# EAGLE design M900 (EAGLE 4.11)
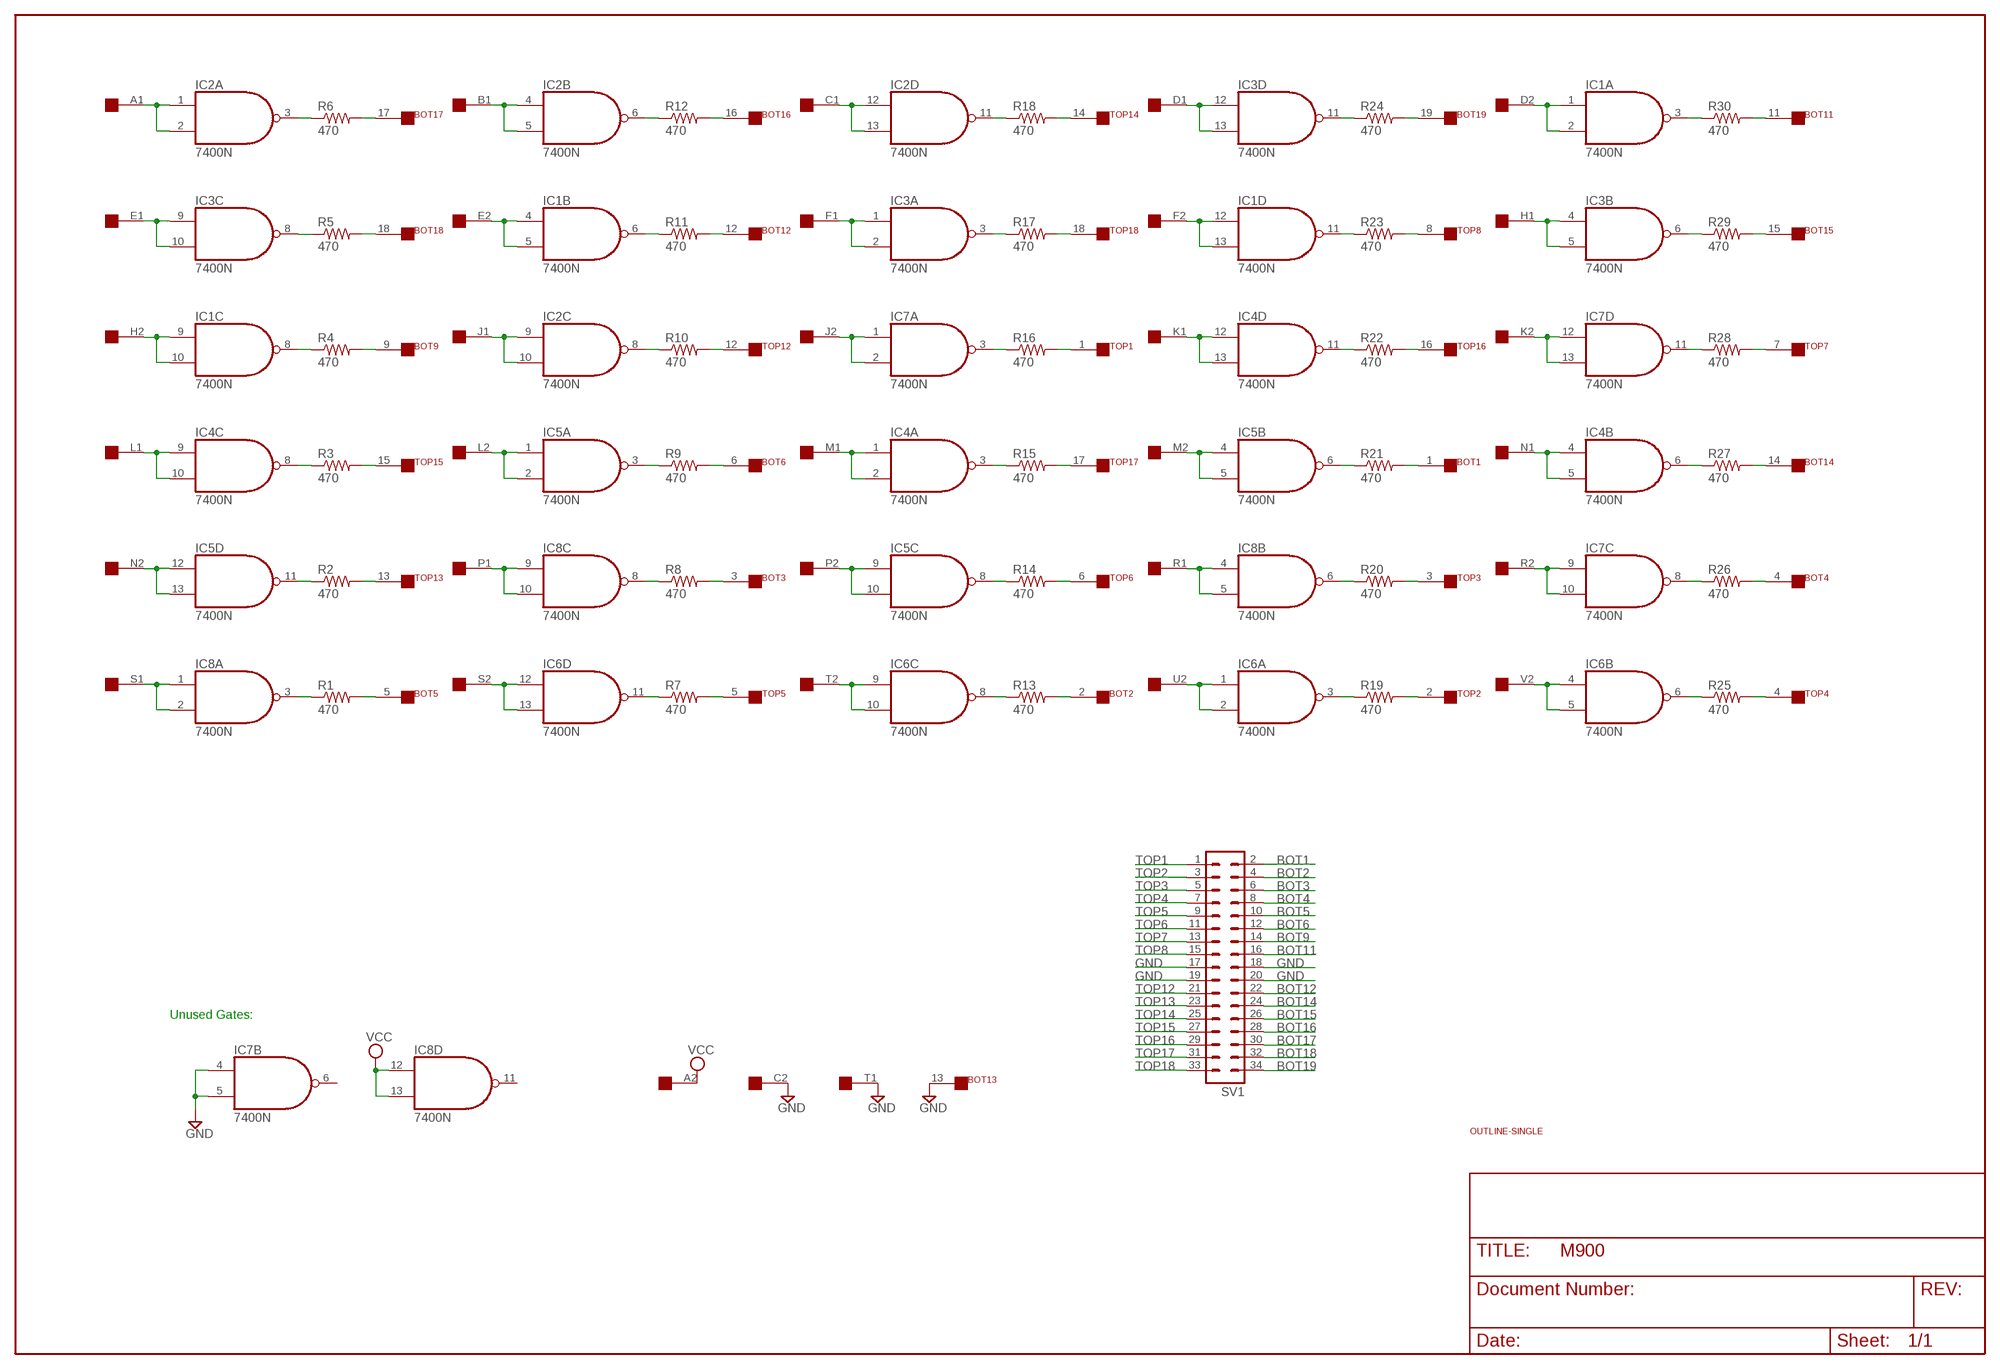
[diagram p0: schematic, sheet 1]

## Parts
BOT  FLEX19  [FLEX19]
EDGE  SINGLE  [EDGE-CON2]
IC1  7400N  [DIL14]
IC2  7400N  [DIL14]
IC3  7400N  [DIL14]
IC4  7400N  [DIL14]
IC5  7400N  [DIL14]
IC6  7400N  [DIL14]
IC7  7400N  [DIL14]
IC8  7400N  [DIL14]
R1  470  R-US_0207/10  [0207/10]
R2  470  R-US_0207/10  [0207/10]
R3  470  R-US_0207/10  [0207/10]
R4  470  R-US_0207/10  [0207/10]
R5  470  R-US_0207/10  [0207/10]
R6  470  R-US_0207/10  [0207/10]
R7  470  R-US_0207/10  [0207/10]
R8  470  R-US_0207/10  [0207/10]
R9  470  R-US_0207/10  [0207/10]
R10  470  R-US_0207/10  [0207/10]
R11  470  R-US_0207/10  [0207/10]
R12  470  R-US_0207/10  [0207/10]
R13  470  R-US_0207/10  [0207/10]
R14  470  R-US_0207/10  [0207/10]
R15  470  R-US_0207/10  [0207/10]
R16  470  R-US_0207/10  [0207/10]
R17  470  R-US_0207/10  [0207/10]
R18  470  R-US_0207/10  [0207/10]
R19  470  R-US_0207/10  [0207/10]
R20  470  R-US_0207/10  [0207/10]
R21  470  R-US_0207/10  [0207/10]
R22  470  R-US_0207/10  [0207/10]
R23  470  R-US_0207/10  [0207/10]
R24  470  R-US_0207/10  [0207/10]
R25  470  R-US_0207/10  [0207/10]
R26  470  R-US_0207/10  [0207/10]
R27  470  R-US_0207/10  [0207/10]
R28  470  R-US_0207/10  [0207/10]
R29  470  R-US_0207/10  [0207/10]
R30  470  R-US_0207/10  [0207/10]
SV1  MA17-2  [MA17-2]
TOP  FLEX19  [FLEX19]
U$2  OUTLINE-SINGLE  [SINGLE]

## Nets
BOT1: BOT.1 R21.2 SV1.2
BOT2: BOT.2 R13.2 SV1.4
BOT3: BOT.3 R8.2 SV1.6
BOT4: BOT.4 R26.2 SV1.8
BOT5: BOT.5 R1.2 SV1.10
BOT6: BOT.6 R9.2 SV1.12
BOT9: BOT.9 R4.2 SV1.14
BOT11: BOT.11 R30.2 SV1.16
BOT12: BOT.12 R11.2 SV1.22
BOT14: BOT.14 R27.2 SV1.24
BOT15: BOT.15 R29.2 SV1.26
BOT16: BOT.16 R12.2 SV1.28
BOT17: BOT.17 R6.2 SV1.30
BOT18: BOT.18 R5.2 SV1.32
BOT19: BOT.19 R24.2 SV1.34
GND [supply]: BOT.13 EDGE.C2 EDGE.T1 IC7.4(B:I0) IC7.5(B:I1) SV1.17 SV1.18 SV1.19 SV1.20
N$1: EDGE.A1 IC2.1(A:I0) IC2.2(A:I1)
N$2: IC2.3(A:O) R6.1
N$3: IC3.8(C:O) R5.1
N$4: IC1.8(C:O) R4.1
N$5: IC4.8(C:O) R3.1
N$6: IC5.11(D:O) R2.1
N$7: EDGE.H2 IC1.9(C:I0) IC1.10(C:I1)
N$8: EDGE.S1 IC8.1(A:I0) IC8.2(A:I1)
N$9: EDGE.N2 IC5.12(D:I0) IC5.13(D:I1)
N$10: EDGE.L1 IC4.9(C:I0) IC4.10(C:I1)
N$11: EDGE.E1 IC3.9(C:I0) IC3.10(C:I1)
N$12: EDGE.P1 IC8.9(C:I0) IC8.10(C:I1)
N$13: EDGE.B1 IC2.4(B:I0) IC2.5(B:I1)
N$14: EDGE.E2 IC1.4(B:I0) IC1.5(B:I1)
N$15: EDGE.J1 IC2.9(C:I0) IC2.10(C:I1)
N$16: EDGE.L2 IC5.1(A:I0) IC5.2(A:I1)
N$17: EDGE.S2 IC6.12(D:I0) IC6.13(D:I1)
N$18: IC8.8(C:O) R8.1
N$19: IC5.3(A:O) R9.1
N$20: IC2.8(C:O) R10.1
N$21: IC1.6(B:O) R11.1
N$22: IC2.6(B:O) R12.1
N$23: IC6.11(D:O) R7.1
N$24: IC8.3(A:O) R1.1
N$25: EDGE.P2 IC5.9(C:I0) IC5.10(C:I1)
N$26: EDGE.C1 IC2.12(D:I0) IC2.13(D:I1)
N$27: EDGE.F1 IC3.1(A:I0) IC3.2(A:I1)
N$28: EDGE.J2 IC7.1(A:I0) IC7.2(A:I1)
N$29: EDGE.M1 IC4.1(A:I0) IC4.2(A:I1)
N$30: EDGE.T2 IC6.9(C:I0) IC6.10(C:I1)
N$31: IC6.8(C:O) R13.1
N$32: IC5.8(C:O) R14.1
N$33: IC4.3(A:O) R15.1
N$34: IC7.3(A:O) R16.1
N$35: IC2.11(D:O) R18.1
N$36: IC3.3(A:O) R17.1
N$37: IC6.3(A:O) R19.1
N$38: IC8.6(B:O) R20.1
N$39: IC5.6(B:O) R21.1
N$40: IC4.11(D:O) R22.1
N$41: IC1.11(D:O) R23.1
N$42: IC3.11(D:O) R24.1
N$43: EDGE.R1 IC8.4(B:I0) IC8.5(B:I1)
N$44: EDGE.F2 IC1.12(D:I0) IC1.13(D:I1)
N$45: EDGE.K1 IC4.12(D:I0) IC4.13(D:I1)
N$46: EDGE.M2 IC5.4(B:I0) IC5.5(B:I1)
N$47: EDGE.U2 IC6.1(A:I0) IC6.2(A:I1)
N$48: EDGE.R2 IC7.9(C:I0) IC7.10(C:I1)
N$49: EDGE.D1 IC3.12(D:I0) IC3.13(D:I1)
N$50: EDGE.D2 IC1.1(A:I0) IC1.2(A:I1)
N$51: EDGE.H1 IC3.4(B:I0) IC3.5(B:I1)
N$52: EDGE.K2 IC7.12(D:I0) IC7.13(D:I1)
N$53: EDGE.N1 IC4.4(B:I0) IC4.5(B:I1)
N$54: EDGE.V2 IC6.4(B:I0) IC6.5(B:I1)
N$55: IC6.6(B:O) R25.1
N$56: IC7.8(C:O) R26.1
N$57: IC4.6(B:O) R27.1
N$58: IC7.11(D:O) R28.1
N$59: IC3.6(B:O) R29.1
N$60: IC1.3(A:O) R30.1
TOP1: R16.2 SV1.1 TOP.1
TOP2: R19.2 SV1.3 TOP.2
TOP3: R20.2 SV1.5 TOP.3
TOP4: R25.2 SV1.7 TOP.4
TOP5: R7.2 SV1.9 TOP.5
TOP6: R14.2 SV1.11 TOP.6
TOP7: R28.2 SV1.13 TOP.7
TOP8: R23.2 SV1.15 TOP.8
TOP12: R10.2 SV1.21 TOP.12
TOP13: R2.2 SV1.23 TOP.13
TOP14: R18.2 SV1.25 TOP.14
TOP15: R3.2 SV1.27 TOP.15
TOP16: R22.2 SV1.29 TOP.16
TOP17: R15.2 SV1.31 TOP.17
TOP18: R17.2 SV1.33 TOP.18
VCC [supply]: EDGE.A2 IC8.12(D:I0) IC8.13(D:I1)
Unconnected: BOT.7 BOT.8 BOT.10 EDGE.B2 EDGE.U1 EDGE.V1 IC7.6(B:O) IC8.11(D:O) TOP.9 TOP.10 TOP.11 TOP.19

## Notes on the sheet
- Unused Gates:

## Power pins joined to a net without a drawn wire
GND: IC1.7(P:GND) IC2.7(P:GND) IC3.7(P:GND) IC4.7(P:GND) IC5.7(P:GND) IC6.7(P:GND) IC7.7(P:GND) IC8.7(P:GND)
VCC: IC1.14(P:VCC) IC2.14(P:VCC) IC3.14(P:VCC) IC4.14(P:VCC) IC5.14(P:VCC) IC6.14(P:VCC) IC7.14(P:VCC) IC8.14(P:VCC)

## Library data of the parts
BOT TOP = dec-con:FLEX19
EDGE = dec-con:SINGLE: Single-Height DEC board
IC1-IC8 = 74xx-jameco:74*00: Quad 2-input NAND gate
R1-R30 = rcl:R-US_: RESISTOR, American symbol
SV1 = con-lstb:MA17-2: PIN HEADER
U$2 = dec-con:OUTLINE-*: Board outlines for DEC boards.

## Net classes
0 default: width 0.381 mm
1 supply: width 0.762 mm

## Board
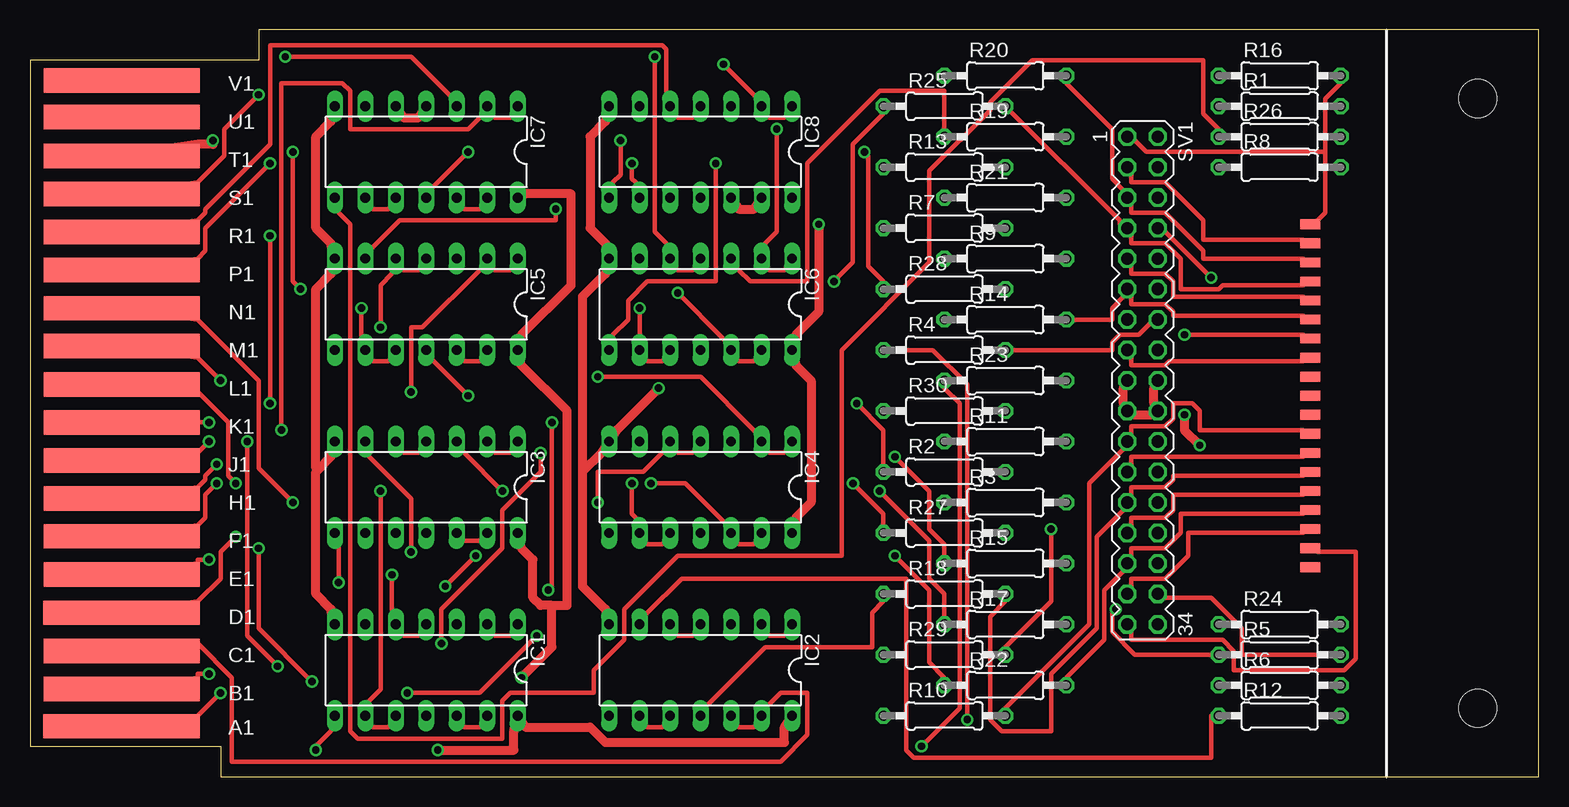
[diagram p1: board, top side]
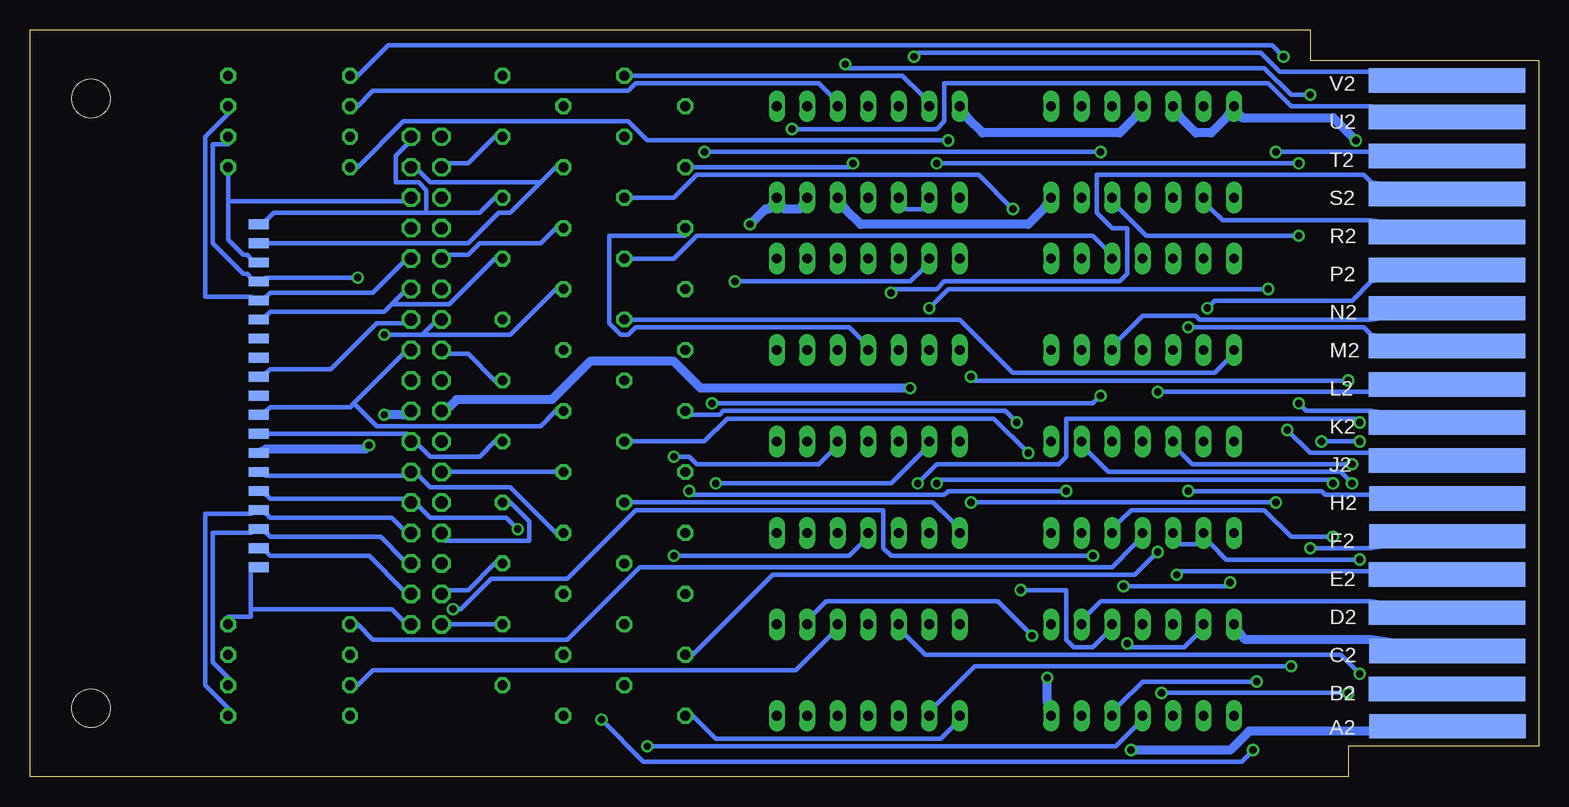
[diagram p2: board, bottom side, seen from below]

Size 125.73 x 62.23 mm. Coordinates in mm from the lower left corner, seen from the top.
Copper layers (1*16): Top 0.035mm / dielectric 1.5mm / Bottom 0.035mm
Design rules "10mils": minimum track width 10mil, minimum drill 24mil, track to track 10mil, track to pad 10mil, pad to pad 10mil, via to via 10mil, smd to smd 10mil, copper to edge 25mil, drill to drill 10mil, minimum pad ring 10mil, minimum via ring 8mil, stop-mask expansion 0mil, vias tented up to drill 0mil, thermal gap 10mil

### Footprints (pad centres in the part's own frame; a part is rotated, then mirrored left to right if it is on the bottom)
FLEX19 = smd 1.676 x 0.813: 1 0,14.287; 2 0,12.7; 3 0,11.113; 4 0,9.525; 5 0,7.938; 6 0,6.35; 7 0,4.763; 8 0,3.175; 9 0,1.587; 10 0,0; 11 0,-1.587; 12 0,-3.175; 13 0,-4.763; 14 0,-6.35; 15 0,-7.938; 16 0,-9.525; 17 0,-11.113; 18 0,-12.7; 19 0,-14.287
EDGE-CON2 = smd 13.017 x 2.032: A1 7.633,4.207; B1 7.639,7.327; C1 7.636,10.489; D1 7.633,13.665; E1 7.642,16.84; F1 7.642,20.041; H1 7.642,23.19; J1 7.642,26.34; K1 7.642,29.515; L1 7.642,32.69; M1 7.642,35.89; N1 7.642,39.04; P1 7.642,42.24; R1 7.642,45.39; S1 7.642,48.565; T1 7.642,51.74; U1 7.642,54.966; V1 7.642,58.026 | smd 13.017 x 2.032 bottom: A2 7.614,4.207; B2 7.642,7.328; C2 7.617,10.49; D2 7.642,13.665; E2 7.642,16.84; F2 7.617,20.041; H2 7.617,23.19; J2 7.642,26.34; K2 7.642,29.515; L2 7.642,32.69; M2 7.642,35.89; N2 7.642,39.04; P2 7.642,42.24; R2 7.642,45.39; S2 7.642,48.565; T2 7.642,51.74; U2 7.642,54.966; V2 7.642,58.026
DIL14 = drill 0.813 long: 1 -7.62,-3.81; 2 -5.08,-3.81; 3 -2.54,-3.81; 4 0,-3.81; 5 2.54,-3.81; 6 5.08,-3.81; 7 7.62,-3.81; 8 7.62,3.81; 9 5.08,3.81; 10 2.54,3.81; 11 0,3.81; 12 -2.54,3.81; 13 -5.08,3.81; 14 -7.62,3.81
0207/10 = drill 0.813 octagon: 1 -5.08,0; 2 5.08,0
MA17-2 = drill 1.016 octagon: 1 -20.32,-1.27; 2 -20.32,1.27; 3 -17.78,-1.27; 4 -17.78,1.27; 5 -15.24,-1.27; 6 -15.24,1.27; 7 -12.7,-1.27; 8 -12.7,1.27; 9 -10.16,-1.27; 10 -10.16,1.27; 11 -7.62,-1.27; 12 -7.62,1.27; 13 -5.08,-1.27; 14 -5.08,1.27; 15 -2.54,-1.27; 16 -2.54,1.27; 17 0,-1.27; 18 0,1.27; 19 2.54,-1.27; 20 2.54,1.27; 21 5.08,-1.27; 22 5.08,1.27; 23 7.62,-1.27; 24 7.62,1.27; 25 10.16,-1.27; 26 10.16,1.27; 27 12.7,-1.27; 28 12.7,1.27; 29 15.24,-1.27; 30 15.24,1.27; 31 17.78,-1.27; 32 17.78,1.27; 33 20.32,-1.27; 34 20.32,1.27
SINGLE = hole 3.175: 120.65,56.515; 120.65,5.715

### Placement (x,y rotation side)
BOT  106.68,31.75 0 bottom
EDGE  0,0 0 top
IC1  33.02,8.89 180 top
IC2  55.88,8.89 180 top
IC3  33.02,24.13 180 top
IC4  55.88,24.13 180 top
IC5  33.02,39.37 180 top
IC6  55.88,39.37 180 top
IC7  33.02,52.07 180 top
IC8  55.88,52.07 180 top
R1  104.14,55.88 0 top
R2  76.2,25.4 0 top
R3  81.28,22.86 0 top
R4  76.2,35.56 0 top
R5  104.14,10.16 0 top
R6  104.14,7.62 0 top
R7  76.2,45.72 0 top
R8  104.14,50.8 0 top
R9  81.28,43.18 0 top
R10  76.2,5.08 0 top
R11  81.28,27.94 0 top
R12  104.14,5.08 0 top
R13  76.2,50.8 0 top
R14  81.28,38.1 0 top
R15  81.28,17.78 0 top
R16  104.14,58.42 0 top
R17  81.28,12.7 0 top
R18  76.2,15.24 0 top
R19  81.28,53.34 0 top
R20  81.28,58.42 0 top
R21  81.28,48.26 0 top
R22  81.28,7.62 0 top
R23  81.28,33.02 0 top
R24  104.14,12.7 0 top
R25  76.2,55.88 0 top
R26  104.14,53.34 0 top
R27  76.2,20.32 0 top
R28  76.2,40.64 0 top
R29  76.2,10.16 0 top
R30  76.2,30.48 0 top
SV1  92.71,33.02 270 top
TOP  106.68,31.75 0 top
U$2  0,0 0 top

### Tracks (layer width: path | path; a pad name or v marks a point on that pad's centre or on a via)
BOT1
  Bottom 0.381: 92.71,46.99 88.27,46.99 87,48.26 R21.2 | 92.71,46.99 105.41,46.99 106.05,46.35 BOT.1 | 92.71,46.99 92.71,48.9 93.35,49.53 95.25,49.53 95.25,51.75 94.3,52.7 SV1.2
BOT2
  Bottom 0.381: 83.19,49.53 81.92,50.8 R13.2 | 83.19,49.53 85.73,46.99 86.68,46.99 89.22,44.45 BOT.2 | 83.19,49.53 92.39,49.53 93.35,50.48 SV1.4
BOT3
  Bottom 0.381: 109.22,47.94 109.22,44.77 107.95,43.5 107.63,43.5 107.32,43.18 BOT.3 | 109.22,47.94 R8.2 | 109.22,47.94 94.62,47.94 SV1.6
BOT4  (via drill 0.61)
  Top 0.381: v98.43,41.59 94.62,45.4 SV1.8
  Bottom 0.381: R26.2 109.22,52.7 110.49,52.7 110.49,44.45 107.95,41.91 107.63,41.91 107.32,41.59 BOT.4 106.05,41.59 v98.43,41.59
BOT5
  Bottom 0.381: SV1.10 94.62,42.86 97.16,40.32 105.73,40.32 106.05,40.01 BOT.5 107.32,40.01 111.13,40.01 111.13,53.34 109.22,55.24 R1.2
BOT6
  Bottom 0.381: 95.57,39.37 94.62,40.32 SV1.12 | 95.57,39.37 96.2,38.73 105.73,38.73 106.05,38.42 BOT.6 | 95.57,39.37 90.81,39.37 87,43.18 R9.2
BOT9
  Top 0.381: R4.2 90.17,35.56 90.17,36.2 90.81,36.83 92.39,36.83 93.35,37.78 SV1.14
  Bottom 0.381: BOT.9 106.05,33.66 105.73,33.97 100.65,33.97 96.84,37.78 94.62,37.78 SV1.14
BOT11
  Bottom 0.381: 98.74,31.11 94.62,35.24 SV1.16 | 98.74,31.11 99.06,30.8 105.73,30.8 106.05,30.48 BOT.11 | 98.74,31.11 96.84,29.21 83.19,29.21 81.92,30.48 R30.2
BOT12
  Bottom 0.381: BOT.12 94.3,28.57 SV1.22 93.35,27.62 92.39,26.67 88.27,26.67 87,27.94 R11.2
BOT14
  Bottom 0.381: BOT.14 106.05,25.08 94.62,25.08 SV1.24 93.35,25.08 92.39,24.13 85.73,24.13 81.92,20.32 R27.2
BOT15  (via drill 0.61)
  Top 0.381: v85.09,20.64 85.09,14.61 81.28,10.79 R29.2
  Bottom 0.381: BOT.15 106.05,23.5 105.73,23.18 94.62,23.18 SV1.26 93.35,22.54 92.39,21.59 86.04,21.59 v85.09,20.64
BOT16
  Bottom 0.381: SV1.28 94.62,20.64 95.57,21.59 105.73,21.59 106.05,21.91 BOT.16 107.32,21.91 111.13,21.91 111.13,7.62 109.22,5.71 R12.2
BOT17
  Bottom 0.381: SV1.30 94.62,18.1 96.52,20 105.73,20 106.05,20.32 BOT.17 107.32,20.32 110.49,20.32 110.49,9.53 109.22,8.26 R6.2
BOT18
  Top 0.381: R5.2 100.97,10.16 100.97,12.38 98.43,14.92 94.62,14.92 SV1.32
  Bottom 0.381: BOT.18 106.05,18.73 105.73,18.41 97.47,18.41 94.62,15.56 SV1.32
BOT19
  Bottom 0.381: 107.32,13.97 107.32,13.34 109.22,13.34 R24.2 | 107.32,13.97 107.32,17.14 BOT.19 | 107.32,13.97 95.57,13.97 94.62,13.02 SV1.34
GND  (via drill 0.61)
  Top 0.762: IC7.5 31.12,54.93 32.39,54.93 IC7.4 | IC7.7 25.08,54.61 23.81,53.34 23.81,45.72 25.08,44.45 IC5.7 25.08,41.91 23.81,40.64 23.81,25.72 23.97,25.56 | 23.97,25.56 23.81,25.4 23.81,15.24 25.08,13.97 IC1.7 | 23.97,25.56 25.08,26.67 IC3.7 | v15.24,53.02 15.24,52.7 13.97,52.7 EDGE.T1 | v97.47,27.62 96.2,28.89 v96.2,30.16 | SV1.17 91.12,32.38 91.12,31.11 SV1.19 92.08,30.16 93.35,30.16 SV1.20 93.66,31.11 93.66,32.38 SV1.18 | IC8.7 47.94,54.61 46.67,53.34 46.67,45.72 47.94,44.45 IC6.7 47.94,41.91 46.04,40.01 46.04,25.4 | 46.04,25.4 46.04,15.88 47.94,13.97 IC2.7 | 46.04,25.4 47.63,26.99 IC4.7 48.9,28.89 v52.39,32.38
  Bottom 0.762: IC7.5 29.85,54.93 28.58,53.66 27.31,53.66 26.04,54.93 IC7.7 24.77,54.93 17.15,54.93 v15.24,53.02 | IC1.7 24.77,11.75 24.45,11.43 13.97,11.43 EDGE.C2 | v97.47,27.62 97.79,27.3 106.05,27.3 BOT.13 | v96.2,30.16 94.62,30.16 SV1.20 | v52.39,32.38 69.85,32.38 72.07,34.61 79.06,34.61 82.23,31.43 90.17,31.43 90.81,30.8 SV1.19 | IC7.4 33.66,54.93 34.93,53.66 46.36,53.66 47.63,54.93 IC8.7
N$1  (via drill 0.61)
  Top 0.381: IC2.2 61.6,11.75 62.87,11.75 IC2.1 | v42.23,11.75 37.47,6.99 v31.43,6.99 | v15.88,6.99 13.97,5.08 EDGE.A1
  Bottom 0.381: v42.23,11.75 45.09,14.61 59.37,14.61 60.33,13.65 IC2.2 | v15.88,6.99 v31.43,6.99
N$2
  Bottom 0.381: IC2.3 59.06,11.75 61.91,8.89 97.16,8.89 98.43,7.62 R6.1
N$3  (via drill 0.61)
  Top 0.381: v25.72,16.19 25.72,19.05 IC3.8 | v34.61,15.88 v37.15,18.41 | v90.49,13.97 90.17,13.65 90.17,12.06 92.08,10.16 R5.1
  Bottom 0.381: v25.72,16.19 26.04,15.88 v34.61,15.88 | v37.15,18.41 53.98,18.41 54.61,19.05 54.61,22.23 75.25,22.23 80.96,16.51 87.31,16.51 89.85,13.97 v90.49,13.97
N$4  (via drill 0.61)
  Top 0.381: v23.81,2.22 23.81,2.54 25.08,3.81 IC1.8 | v78.11,4.76 78.11,32.7 75.25,35.56 R4.1
  Bottom 0.381: v23.81,2.22 24.77,1.27 74.61,1.27 v78.11,4.76
N$5
  Bottom 0.381: IC4.8 48.9,21.27 50.48,22.86 R3.1
N$6  (via drill 0.61)
  Top 0.381: v36.51,31.75 33.66,34.61 IC5.11 | v68.9,31.11 71.12,28.89 R2.1
  Bottom 0.381: v36.51,31.75 37.15,31.11 v68.9,31.11
N$7  (via drill 0.61)
  Top 0.381: IC1.10 29.85,4.13 28.58,4.13 IC1.9 28.26,6.35 29.21,7.3 v29.21,23.81
  Bottom 0.381: v29.21,23.81 18.1,23.81 17.78,23.5 13.97,23.5 EDGE.H2
N$8  (via drill 0.61)
  Top 0.381: IC8.1 62.87,54.93 61.6,54.93 IC8.2 60.33,56.83 v57.79,59.37 | v19.05,56.83 16.19,53.98 16.19,51.75 13.97,49.53 EDGE.S1
  Bottom 0.381: v57.79,59.37 57.47,59.05 22.86,59.05 20.64,56.83 v19.05,56.83
N$9
  Top 0.381: IC5.12 36.2,34.61 37.47,34.61 IC5.13
  Bottom 0.381: IC5.12 34.93,36.51 33.02,38.42 28.58,38.42 28.26,38.1 13.97,38.1 EDGE.N2
N$10  (via drill 0.61)
  Top 0.381: IC4.10 52.71,19.37 51.44,19.37 IC4.9 50.48,21.59 50.17,21.91 v50.17,24.45 | v17.15,24.45 16.51,25.08 16.51,29.53 13.97,32.07 EDGE.L1
  Bottom 0.381: v50.17,24.45 49.85,24.77 17.46,24.77 v17.15,24.45
N$11  (via drill 0.61)
  Top 0.381: v14.92,18.1 13.97,18.1 13.97,17.78 EDGE.E1
  Bottom 0.381: IC3.10 29.85,19.37 28.58,19.37 IC3.9 27.31,19.37 26.04,18.1 v14.92,18.1
N$12  (via drill 0.61)
  Top 0.381: v50.17,51.12 50.17,49.85 50.48,49.53 IC8.9 | v20,51.12 14.61,45.72 14.61,43.81 13.97,43.18 EDGE.P1
  Bottom 0.381: IC8.9 51.44,47.31 52.71,47.31 IC8.10 | v20,51.12 v50.17,51.12
N$13  (via drill 0.61)
  Top 0.381: IC2.5 53.98,11.75 55.25,11.75 IC2.4 | v14.92,8.57 13.97,8.57 13.97,8.26 EDGE.B1
  Bottom 0.381: v14.92,8.57 16.51,10.16 51.12,10.16 52.71,11.75 IC2.5
N$14  (via drill 0.61)
  Top 0.381: IC1.4 32.39,11.75 31.12,11.75 IC1.5 30.16,13.97 v30.16,16.83
  Bottom 0.381: v30.16,16.83 29.85,17.14 13.97,17.14 EDGE.E2
N$15  (via drill 0.61)
  Top 0.381: IC2.9 51.44,4.13 52.71,4.13 IC2.10 | v20.64,9.21 18.1,11.75 v18.1,27.94 | v14.92,27.94 13.97,26.99 EDGE.J1
  Bottom 0.381: v20.64,9.21 46.99,9.21 50.17,6.03 IC2.9 | v18.1,27.94 v14.92,27.94
N$16  (via drill 0.61)
  Top 0.381: IC5.1 40.01,42.23 38.74,42.23 IC5.2 37.47,42.23 32.7,37.47 31.75,37.47 v31.75,32.07
  Bottom 0.381: v31.75,32.07 13.97,32.07 EDGE.L2
N$17  (via drill 0.61)
  Top 0.381: IC6.13 60.33,34.61 59.06,34.61 IC6.12 57.79,36.51 v53.98,40.32
  Bottom 0.381: v53.98,40.32 53.66,40.64 50.17,40.64 49.53,41.27 34.93,41.27 34.29,41.91 34.29,45.72 35.56,45.72 36.83,46.99 36.83,50.16 14.61,50.16 13.97,49.53 EDGE.S2
N$18  (via drill 0.61)
  Top 0.381: v49.21,53.02 49.21,50.16 48.58,49.53 IC8.8
  Bottom 0.381: v49.21,53.02 74.3,53.02 75.88,54.61 94.62,54.61 98.43,50.8 R8.1
N$19
  Bottom 0.381: IC5.3 36.2,44.13 37.15,45.09 70.17,45.09 72.07,43.18 R9.1
N$20
  Bottom 0.381: IC2.8 48.9,4.13 49.85,3.17 68.58,3.17 70.49,5.08 R10.1
N$21  (via drill 0.61)
  Top 0.381: v34.29,11.11 34.29,13.97 39.37,19.05 39.37,22.23 42.55,25.4 v42.55,26.99
  Bottom 0.381: v34.29,11.11 33.97,10.79 29.53,10.79 28.58,11.75 IC1.6 | v42.55,26.99 45.4,29.84 67.63,29.84 69.53,27.94 R11.1
N$22
  Top 0.381: IC2.6 51.44,13.65 54.29,16.51 73.03,16.51 73.03,2.22 73.66,1.59 98.43,1.59 98.43,5.08 R12.1
N$23
  Bottom 0.381: IC6.11 56.52,36.51 57.47,37.47 75.25,37.47 75.88,36.83 76.52,36.83 77.47,37.78 77.47,45.09 71.12,45.09 R7.1
N$24
  Bottom 0.381: IC8.3 59.06,56.83 60.01,57.78 75.25,57.78 75.88,57.15 97.16,57.15 98.43,55.88 R1.1
N$25  (via drill 0.61)
  Top 0.381: IC5.10 29.85,34.61 28.58,34.61 IC5.9 27.62,36.83 v27.62,39.05
  Bottom 0.381: v27.62,39.05 26.99,39.69 15.56,39.69 13.97,41.27 EDGE.P2
N$26
  Top 0.381: IC2.12 59.06,4.13 60.33,4.13 IC2.13 61.6,6.03 62.55,6.99 64.77,6.99 64.77,3.49 62.55,1.27 16.83,1.27 16.83,8.26 13.97,11.11 EDGE.C1
N$27  (via drill 0.61)
  Top 0.381: IC3.2 38.74,26.99 40.01,26.99 IC3.1 | v15.56,24.45 14.61,23.5 14.61,21.59 13.97,20.95 EDGE.F1
  Bottom 0.381: v15.56,24.45 16.51,25.4 35.88,25.4 37.47,26.99 IC3.2
N$28  (via drill 0.61)
  Top 0.381: IC7.1 40.01,54.93 38.74,54.93 IC7.2 37.47,54.93 36.51,53.98 26.67,53.98 26.67,57.15 26.04,57.78 20.96,57.78 v20.96,28.89
  Bottom 0.381: v20.96,28.89 19.05,26.99 13.97,26.99 EDGE.J2
N$29  (via drill 0.61)
  Top 0.381: IC4.1 62.87,26.99 61.6,26.99 IC4.2 60.33,28.89 55.88,33.34 v47.31,33.34 | v15.88,33.02 13.97,34.92 EDGE.M1
  Bottom 0.381: v47.31,33.34 46.99,33.02 v15.88,33.02
N$30  (via drill 0.61)
  Top 0.381: IC6.10 52.71,34.61 51.44,34.61 IC6.9 v50.8,39.05 | v22.54,40.64 21.91,41.27 v21.91,52.07
  Bottom 0.381: v50.8,39.05 49.21,40.64 v22.54,40.64 | v21.91,52.07 13.97,52.07 EDGE.T2
N$31  (via drill 0.61)
  Top 0.381: v57.15,51.12 57.15,41.27 51.44,41.27 49.85,39.69 49.85,38.1 48.58,36.83 IC6.8
  Bottom 0.381: v57.15,51.12 57.47,50.8 R13.1
N$32
  Bottom 0.381: IC5.8 26.04,34.61 26.99,33.66 43.82,33.66 48.26,38.1 R14.1
N$33  (via drill 0.61)
  Top 0.381: v72.07,26.67 74.93,23.81 74.93,20.64 76.2,19.37 R15.1
  Bottom 0.381: v72.07,26.67 70.8,26.67 70.17,26.04 60.01,26.04 59.06,26.99 IC4.3
N$34  (via drill 0.61)
  Top 0.381: v21.27,60.01 31.75,60.01 34.93,56.83 IC7.3
  Bottom 0.381: v21.27,60.01 22.23,60.96 95.89,60.96 98.43,58.42 R16.1
N$35
  Top 0.381: IC2.11 56.52,6.03 61.28,10.79 70.17,10.79 70.17,13.65 71.12,14.61 R18.1
N$36  (via drill 0.61)
  Top 0.381: v39.37,23.81 36.2,26.99 IC3.3 | v70.8,23.81 74.93,19.68 74.93,16.51 76.2,15.24 R17.1
  Bottom 0.381: v39.37,23.81 49.21,23.81 49.53,23.5 70.49,23.5 v70.8,23.81
N$37
  Top 0.381: IC6.3 59.06,42.23 60.01,41.27 64.77,41.27 64.77,51.12 70.8,57.15 76.2,57.15 R19.1
N$38
  Bottom 0.381: IC8.6 51.44,56.83 53.02,58.42 R20.1
N$39  (via drill 0.61)
  Top 0.381: v43.82,47.31 43.82,46.35 30.8,46.35 28.58,44.13 IC5.6
  Bottom 0.381: v43.82,47.31 46.67,50.16 70.17,50.16 72.07,48.26 R21.1
N$40  (via drill 0.61)
  Top 0.381: v72.07,18.41 74.93,15.56 74.93,9.53 76.2,8.26 R22.1
  Bottom 0.381: v72.07,18.41 57.47,18.41 56.52,19.37 IC4.11
N$41  (via drill 0.61)
  Top 0.381: v74.3,2.54 77.47,5.71 77.47,31.11 76.2,32.38 R23.1
  Bottom 0.381: v74.3,2.54 35.24,2.54 33.66,4.13 IC1.11
N$42
  Bottom 0.381: IC3.11 33.66,19.37 35.56,17.46 74.93,17.46 80.96,11.43 97.16,11.43 98.43,12.7 R24.1
N$43
  Top 0.381: IC8.4 55.25,54.93 53.98,54.93 IC8.5 53.02,57.15 53.02,60.64 52.71,60.96 20,60.96 20,52.7 14.61,47.31 14.61,46.99 13.97,46.35 EDGE.R1
N$44  (via drill 0.61)
  Top 0.381: IC1.12 36.2,4.13 37.47,4.13 IC1.13 | v23.5,7.94 19.05,12.38 v19.05,19.05
  Bottom 0.381: v23.5,7.94 33.02,7.94 34.93,6.03 IC1.12 | v19.05,19.05 13.97,19.05 EDGE.F2
N$45  (via drill 0.61)
  Top 0.381: IC4.13 60.33,19.37 59.06,19.37 IC4.12 57.79,21.27 54.61,24.45 v51.75,24.45 | v14.92,29.53 13.97,29.53 EDGE.K1
  Bottom 0.381: v51.75,24.45 50.17,26.04 40.01,26.04 39.37,26.67 39.37,29.84 15.24,29.84 v14.92,29.53
N$46  (via drill 0.61)
  Top 0.381: IC5.4 32.39,42.23 31.12,42.23 IC5.5 30.16,41.91 29.21,40.96 v29.21,37.47
  Bottom 0.381: v29.21,37.47 14.61,37.47 13.97,36.83 EDGE.M2
N$47  (via drill 0.61)
  Top 0.381: IC6.1 62.87,42.23 61.6,42.23 IC6.2 61.28,44.45 62.23,45.4 v62.23,53.98
  Bottom 0.381: v62.23,53.98 50.17,53.98 49.53,54.61 49.53,57.78 22.54,57.78 20.64,55.88 13.97,55.88 EDGE.U2
N$48
  Top 0.381: IC7.9 28.58,47.31 29.85,47.31 IC7.10
  Bottom 0.381: IC7.9 27.31,47.31 26.35,46.35 13.97,46.35 EDGE.R2
N$49  (via drill 0.61)
  Top 0.381: IC3.12 36.2,19.68 37.47,19.68 IC3.13 | v17.15,20 15.88,18.73 15.88,16.51 13.97,14.61 EDGE.D1
  Bottom 0.381: v17.15,20 20.64,20 22.86,22.23 33.97,22.23 34.93,21.27 IC3.12
N$50
  Top 0.381: IC1.2 38.74,11.75 40.01,11.75 IC1.1
  Bottom 0.381: IC1.2 37.47,13.65 36.51,14.61 13.97,14.61 EDGE.D2
N$51  (via drill 0.61)
  Top 0.381: IC3.5 31.12,26.99 32.39,26.99 IC3.4 | v15.56,26.04 14.61,25.08 14.61,24.77 13.97,24.13 EDGE.H1
  Bottom 0.381: v15.56,26.04 28.89,26.04 29.85,26.99 IC3.5
N$52  (via drill 0.61)
  Top 0.381: IC7.12 36.2,47.31 37.47,47.31 IC7.13 | v20,31.11 v20,45.09
  Bottom 0.381: v20,45.09 32.7,45.09 34.93,47.31 IC7.12 | v20,31.11 19.37,30.48 13.97,30.48 EDGE.K2
N$53  (via drill 0.61)
  Top 0.381: IC4.4 55.25,26.99 53.98,26.99 IC4.5 52.71,26.99 51.12,25.4 47.31,25.4 v47.31,22.86 | v21.91,22.86 19.05,25.72 19.05,33.02 13.97,38.1 EDGE.N1
  Bottom 0.381: v21.91,22.86 v47.31,22.86
N$54  (via drill 0.61)
  Top 0.381: IC6.4 55.25,42.23 53.98,42.23 IC6.5 53.02,44.45 52.07,45.4 v52.07,60.01
  Bottom 0.381: v52.07,60.01 51.75,60.33 23.18,60.33 21.59,58.74 13.97,58.74 EDGE.V2
N$55  (via drill 0.61)
  Top 0.381: v66.99,41.27 68.58,42.86 68.58,52.7 71.12,55.24 R25.1
  Bottom 0.381: v66.99,41.27 52.39,41.27 51.44,42.23 IC6.6
N$56
  Top 0.381: IC7.8 25.72,46.99 26.67,46.04 26.67,3.81 27.31,3.17 39.37,3.17 39.37,6.35 40.01,6.99 46.99,6.99 46.99,8.89 49.53,11.43 49.53,13.97 53.98,18.41 67.63,18.41 67.63,35.56 74.93,42.86 74.93,50.48 80.01,55.56 80.01,56.2 83.5,59.69 97.79,59.69 97.79,55.24 99.06,53.98 R26.1
N$57  (via drill 0.61)
  Top 0.381: v68.58,24.45 71.12,21.91 R27.1
  Bottom 0.381: v68.58,24.45 53.98,24.45 51.44,26.99 IC4.6
N$58  (via drill 0.61)
  Top 0.381: v36.51,52.07 33.66,49.21 IC7.11 | v69.53,52.07 69.85,51.75 69.85,42.55 71.12,41.27 R28.1
  Bottom 0.381: v36.51,52.07 v69.53,52.07
N$59  (via drill 0.61)
  Top 0.381: v31.75,18.73 31.75,23.18 28.26,26.67 IC3.6
  Bottom 0.381: v31.75,18.73 33.66,16.83 63.82,16.83 70.49,10.16 R29.1
N$60  (via drill 0.61)
  Top 0.381: v43.18,15.56 43.5,15.88 v43.5,29.53
  Bottom 0.381: v43.18,15.56 39.37,15.56 39.37,11.43 38.74,10.79 37.15,10.79 36.2,11.75 IC1.3 | v43.5,29.53 44.45,30.48 67.95,30.48 68.26,30.16 70.8,30.16 R30.1
TOP1
  Top 0.381: 107.95,52.07 107.95,56.52 109.22,57.78 R16.2 | 107.95,52.07 107.95,46.99 107.32,46.35 TOP.1 | 107.95,52.07 93.03,52.07 92.08,53.02 SV1.1
TOP2
  Top 0.381: TOP.2 106.05,44.77 97.79,44.77 97.79,46.35 94.62,49.53 91.76,49.53 91.76,50.16 SV1.3
  Bottom 0.381: R19.2 87,53.34 89.22,51.12 90.81,51.12 SV1.3
TOP3
  Top 0.381: TOP.3 106.05,43.18 97.79,43.18 97.79,43.81 94.62,46.99 91.76,46.99 91.76,47.62 SV1.5 91.12,48.9 90.17,49.85 90.17,53.98 86.36,57.78 R20.2
TOP4
  Top 0.381: TOP.4 106.05,40.96 99.38,40.96 99.06,40.64 95.89,40.64 95.89,43.18 94.62,44.45 91.76,44.45 91.76,45.09 SV1.7 90.81,46.04 90.81,46.35 R25.2
TOP5
  Top 0.381: TOP.5 106.05,40.01 95.25,40.01 95.25,41.27 94.62,41.91 91.76,41.91 91.76,42.55 SV1.9
  Bottom 0.381: R7.2 81.92,45.72 83.19,44.45 88.27,44.45 89.22,43.5 90.81,43.5 SV1.9
TOP6
  Top 0.381: TOP.6 106.05,38.42 95.25,38.42 95.25,38.73 94.62,39.37 91.76,39.37 91.76,40.01 SV1.11 91.12,40.01 90.17,39.05 90.17,38.1 R14.2
TOP7  (via drill 0.61)
  Top 0.381: v96.2,36.83 106.05,36.83 TOP.7
  Bottom 0.381: 93.03,36.83 v96.2,36.83 | 93.03,36.83 92.08,37.78 SV1.13 | 93.03,36.83 85.73,36.83 81.92,40.64 R28.2
TOP8
  Top 0.381: TOP.8 106.05,34.61 94.93,34.61 94.62,34.29 91.76,34.29 91.76,34.92 SV1.15
  Bottom 0.381: R23.2 87,33.02 89.22,35.24 90.81,35.24 SV1.15
TOP12
  Top 0.381: TOP.12 106.05,28.89 97.47,28.89 97.47,30.48 96.84,31.11 95.25,31.11 95.25,29.84 94.62,29.21 91.76,29.21 91.76,28.57 SV1.21 91.12,27.3 88.27,24.45 88.27,12.7 81.28,5.71 R10.2
TOP13
  Top 0.381: TOP.13 106.05,26.67 91.76,26.67 91.76,26.04 SV1.23
  Bottom 0.381: R2.2 SV1.23
TOP14
  Top 0.381: TOP.14 106.05,25.08 95.25,25.08 95.25,24.77 94.62,24.13 91.76,24.13 91.76,23.5 SV1.25 91.12,22.23 88.9,20 88.9,12.38 85.09,8.57 85.09,3.81 80.96,3.81 80.01,4.76 80.01,13.34 81.28,14.61 R18.2
TOP15
  Top 0.381: TOP.15 106.05,23.5 95.25,23.5 95.25,22.23 94.62,21.59 91.76,21.59 91.76,20.95 SV1.27
  Bottom 0.381: R3.2 85.73,22.86 84.14,21.27 84.14,19.68 91.12,19.68 SV1.27
TOP16
  Top 0.381: TOP.16 106.05,21.91 95.89,21.91 95.89,20.32 94.62,19.05 91.76,19.05 91.76,18.41 SV1.29 91.12,17.14 89.54,15.56 89.54,11.43 86.36,8.26 R22.2
TOP17
  Top 0.381: TOP.17 106.05,20.32 96.52,20.32 96.52,18.41 94.62,16.51 91.76,16.51 91.76,15.88 SV1.31
  Bottom 0.381: R15.2 87,17.78 89.22,15.56 90.81,15.56 SV1.31
TOP18
  Top 0.381: TOP.18 107.32,18.73 110.49,18.73 110.49,9.84 109.54,8.89 100.33,8.89 100.33,10.48 99.38,11.43 91.76,11.43 91.76,12.06 SV1.33
  Bottom 0.381: R17.2 SV1.33
VCC  (via drill 0.61)
  Top 0.762: IC2.14 62.87,4.13 62.87,2.86 47.94,2.86 46.67,4.13 41.28,4.13 IC1.14 40.32,3.81 40.32,2.22 v33.97,2.22 | IC4.14 63.82,21.59 65.09,22.86 65.09,33.02 63.82,34.29 IC6.14 63.82,36.83 65.72,38.73 v65.72,46.04 | IC8.12 59.06,47.31 60.33,47.31 IC8.13 | 43.5,14.29 44.77,14.29 44.77,30.48 40.96,34.29 IC5.14 40.96,36.83 45.09,40.96 45.09,48.58 41.28,48.58 IC7.14 | 43.5,14.29 42.55,14.29 41.91,14.92 41.91,18.1 40.96,19.05 IC3.14 | v40.96,8.26 43.5,10.79 43.5,14.29
  Bottom 0.762: IC8.13 61.6,47.31 62.87,47.31 IC8.14 64.14,47.31 64.45,47.31 v65.72,46.04 | IC8.12 57.79,47.31 56.52,46.04 42.55,46.04 41.28,47.31 IC7.14 | v40.96,8.26 40.96,6.35 IC1.14 | v33.97,2.22 25.72,2.22 24.13,3.81 13.97,3.81 EDGE.A2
